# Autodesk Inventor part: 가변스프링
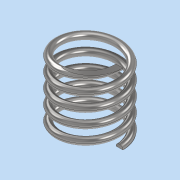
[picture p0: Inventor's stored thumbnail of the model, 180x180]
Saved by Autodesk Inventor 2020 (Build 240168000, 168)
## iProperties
Created: 2021-10
Part Number: 가변스프링
Material: 스테인레스 스틸
Document SubType Name: Modeling
Designer: user
Density: 8 g/cm^3
Appearance: 반연마
Mass: 6.57605 g
Surface Area: 16.726 cm^2
Volume: 0.822006 cm^3
Author: user
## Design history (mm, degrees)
sketch "스케치1"
  geometry: L1 (0, 0)-(8.5, 0); L2 (8.5, 0)-(8.5, 20.5); L3 (8.5, 20.5)-(0, 20.5); L4 (0, 20.5)-(0, 0); C1 r 1 at (8.5, 20.5)
  constraints: 8 end point, 2 parallel, 1 centre point, 1 coincident, 1 horizontal, 1 perpendicular
  dimensions: "d0" = 2 diameter of C1; "d1" = 17 diameter of L2 L4; "d2" = 20.5 distance between parallel lines of L1 L3 (derived)
feature "코일1" sketch "스케치1" pitch "d3" = 10; turns "d5" = 5; dims "d4" = 20.5 (= d2), "d6" = 0, angle "d7" = 90 deg, angle "d8" = 90 deg, "d9" = 0, "d10" = 0
sketch "스케치2"
  geometry: L1 (20.5, 11.854)-(0, 11.854); L2 (0, 11.854)-(0, -11.854); L3 (0, -11.854)-(20.5, -11.854); L4 (20.5, -11.854)-(20.5, 11.854); 2 further points
  constraints: 8 end point, 2 parallel, 1 coincident, 1 horizontal, 1 midpoint, 1 perpendicular
  dimensions: "d11" = 20.5 distance between parallel lines of L2 L4 (= d2)
extrude "돌출1" sketch "스케치2" stored distance "d12" = 32.5; taper "d13" = 0 deg
node "솔리드1"
